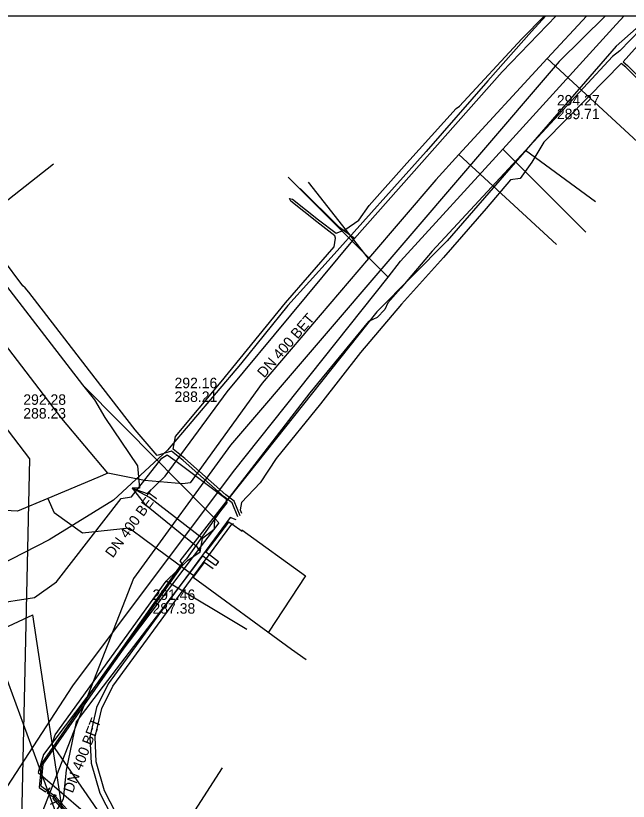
# Model space of a CAD drawing. Extents: x -600309 to -598967, y -1161267 to -1160292.
# Drawn here: x -600042.4 to -599995.5, y -1160352.5 to -1160292.3 of the extents above; entities that cross this region are included whole.
import ezdxf

# ---------------------------------------------------------------- set-up
doc = ezdxf.new("R2010")
doc.units = 0
for name, color, linetype in [('Vrstva 12', 7, 'Continuous'), ('Vrstva 13', 7, 'Continuous'), ('Vrstva 16', 7, 'Continuous'), ('Vrstva 42', 7, 'Continuous'), ('Vrstva 54', 7, 'Continuous'), ('Vrstva 55', 7, 'Continuous'), ('Vrstva 58', 7, 'Continuous'), ('Vrstva 63', 7, 'Continuous'), ('Vrstva 9', 7, 'Continuous')]:
    doc.layers.add(name, color=color, linetype=linetype)

msp = doc.modelspace()

# ---------------------------------------------------------------- linework, layer by layer
at = {"layer": 'Vrstva 12'}
for points in [[(-600016.43, -1160309.39), (-600005.11, -1160296.65), (-600000.985, -1160292.347)], [(-599994.53, -1160293.39), (-599996.1, -1160295.04), (-599996.67, -1160295.46), (-600003.33, -1160302.65)], [(-600003.33, -1160302.65), (-600010.47, -1160310.37), (-600012.87, -1160313.2), (-600013.87, -1160314.33), (-600014.09, -1160314.83), (-600014.67, -1160315.45), (-600015.35, -1160315.75), (-600019.84, -1160321.2), (-600027.14, -1160330.66), (-600027.16, -1160331.67), (-600028.05, -1160332.35)], [(-599997.96, -1160306.59), (-600003.33, -1160302.65)], [(-600050.01, -1160304.22), (-600047.46, -1160307.49), (-600045.75, -1160309.61), (-600037.23, -1160320.58)], [(-600016.43, -1160309.39), (-600017.56, -1160308.55), (-600020.57, -1160305.58)], [(-600033.44, -1160328.5), (-600032.29, -1160328.91), (-600030.92, -1160327.57), (-600026.17, -1160321.13), (-600016.43, -1160309.39)], [(-600037.23, -1160320.58), (-600036.33, -1160321.75), (-600035.54, -1160323.09)], [(-600035.54, -1160323.09), (-600033.04, -1160326.78), (-600032.89, -1160328.49), (-600033.44, -1160328.5)], [(-600033.44, -1160328.5), (-600032.5, -1160329.71), (-600028.55, -1160332.91), (-600028.23, -1160333.36)], [(-600028.05, -1160332.35), (-600032.11, -1160329.22), (-600033.44, -1160328.5)], [(-600028.23, -1160333.36), (-600028.05, -1160332.35)], [(-600030.83, -1160335.62), (-600029.2, -1160334.04), (-600028.23, -1160333.36)], [(-600038.37, -1160349.82), (-600039.57, -1160348.08), (-600039.33, -1160347.38), (-600030.83, -1160335.62)], [(-600024.65, -1160339.32), (-600030.83, -1160335.62)], [(-600034.32, -1160355.66), (-600038.37, -1160349.82)]]:
    msp.add_lwpolyline(points, dxfattribs=at)
at = {"layer": 'Vrstva 13'}
msp.add_line((-600013.85, -1160312.35), (-600021.488, -1160304.701), dxfattribs=at)
for points in [[(-600043.56, -1160352.1), (-600043.347, -1160351.853), (-600037.975, -1160343.616), (-600025.676, -1160327.214), (-600013.85, -1160312.35), (-600012.89, -1160311.139), (-600005.067, -1160302.555), (-599996.39, -1160293.01), (-599995.775, -1160292.347)], [(-600005.067, -1160302.555), (-600003.888, -1160303.735), (-599998.715, -1160308.921)], [(-600069.247, -1160326.845), (-600045.498, -1160308.427), (-600039.453, -1160303.674)], [(-600037.23, -1160320.58), (-600031.43, -1160326.46)], [(-600031.43, -1160326.46), (-600031.15, -1160326.74)], [(-600031.15, -1160326.74), (-600030.6, -1160327.29), (-600027.09, -1160330.85), (-600026.81, -1160331.14), (-600027.91, -1160332.59)], [(-600027.91, -1160332.59), (-600040.22, -1160348.89), (-600040.63, -1160350.26)], [(-600040.63, -1160350.26), (-600030.17, -1160359.23), (-600025.6, -1160362.3), (-600024.69, -1160362.9)], [(-600033.31, -1160361.09), (-600033.125, -1160360.829), (-600030.99, -1160356.83), (-600026.528, -1160349.897)]]:
    msp.add_lwpolyline(points, dxfattribs=at)
at = {"layer": 'Vrstva 16'}
for points in [[(-600035.295, -1160327.352), (-600038.83, -1160323.18), (-600047.7, -1160311.6), (-600047.5, -1160308.26), (-600050.81, -1160304.07), (-600053.96, -1160300), (-600058.4, -1160294.46), (-600059.974, -1160292.347)], [(-599998.63, -1160292.347), (-600001.66, -1160295.63), (-600008.42, -1160302.96), (-600010.2, -1160304.9), (-600015.34, -1160310.92), (-600023.48, -1160320.46), (-600029.01, -1160328.09), (-600029.55, -1160328.17), (-600032.491, -1160327.919)], [(-600001.66, -1160295.63), (-599994.42, -1160302.31)], [(-600008.42, -1160302.96), (-600000.94, -1160309.85)], [(-600015.34, -1160310.92), (-600019.94, -1160305.08)], [(-600032.491, -1160327.919), (-600035.295, -1160327.352), (-600036.066, -1160327.692), (-600039.894, -1160329.296), (-600042.22, -1160330.27), (-600044.183, -1160330.165)], [(-600039.894, -1160329.296), (-600039.418, -1160330.397)], [(-600028.684, -1160335.24), (-600032.359, -1160332.519), (-600033.671, -1160331.547), (-600037.23, -1160331.933), (-600039.418, -1160330.397)], [(-600038.95, -1160354.2), (-600047.112, -1160332.022)]]:
    msp.add_lwpolyline(points, dxfattribs=at)
at = {"layer": 'Vrstva 42'}
for points in [[(-599992.497, -1160292.347), (-599994.33, -1160294.17), (-599995.853, -1160295.866), (-599995.513, -1160296.146), (-599991.99, -1160299.688), (-599991.92, -1160299.9), (-599992.132, -1160299.829), (-599995.647, -1160296.294), (-599995.991, -1160296.011), (-599998.49, -1160298.54), (-600001.91, -1160302.03), (-600002.84, -1160303.55), (-600003.73, -1160304.81), (-600004.47, -1160304.9), (-600006.35, -1160307.11), (-600009.61, -1160310.86), (-600012.82, -1160314.42), (-600015.96, -1160318.13), (-600019.02, -1160322.04), (-600022.42, -1160326.24), (-600023.65, -1160328.08), (-600025.06, -1160329.6), (-600025.162, -1160330.166), (-600025.059, -1160330.405)], [(-600008.38, -1160299.26), (-600003.6, -1160294.12), (-600001.873, -1160292.347)], [(-600025.158, -1160330.611), (-600025.628, -1160329.497), (-600026.256, -1160329.003), (-600029.396, -1160326.233), (-600030.3, -1160325.508), (-600030.13, -1160324.55), (-600026.62, -1160320.35), (-600021.71, -1160314.31), (-600017.98, -1160310.02), (-600017.88, -1160309.38), (-600017.914, -1160309.186), (-600019.292, -1160308.129), (-600021.295, -1160306.543), (-600021.39, -1160306.34), (-600021.171, -1160306.386), (-600019.169, -1160307.971), (-600017.832, -1160308.996), (-600017.15, -1160308.72), (-600016.09, -1160308), (-600015.3, -1160306.87), (-600012.42, -1160303.62), (-600008.638, -1160299.458), (-600008.38, -1160299.26)], [(-600025.342, -1160330.689), (-600025.792, -1160329.623), (-600026.384, -1160329.157), (-600029.524, -1160326.387), (-600030.435, -1160325.655), (-600031.53, -1160325.99), (-600033.21, -1160324.04), (-600036.26, -1160320.09), (-600041.36, -1160313.5), (-600041.618, -1160313.159), (-600041.806, -1160313.022), (-600043.364, -1160310.92)], [(-600025.016, -1160331.803), (-600025.817, -1160331.264), (-600026.068, -1160331.095), (-600027.805, -1160333.371), (-600027.525, -1160333.581), (-600026.823, -1160334.108), (-600026.943, -1160334.268), (-600027.063, -1160334.428), (-600027.763, -1160333.903), (-600028.048, -1160333.689), (-600029.615, -1160335.742), (-600035.648, -1160343.647), (-600037.717, -1160346.386), (-600038.5, -1160350.08), (-600038.715, -1160352.302), (-600038.887, -1160352.567), (-600045.877, -1160363.329), (-600046.428, -1160364.177), (-600046.744, -1160364.664), (-600047.293, -1160365.509), (-600047.104, -1160366.293)], [(-600025.488, -1160330.929), (-600025.934, -1160330.756), (-600029.615, -1160335.742), (-600030.782, -1160337.323), (-600035.284, -1160343.462), (-600036.16, -1160345.27), (-600036.675, -1160347.553), (-600036.577, -1160349.54), (-600035.919, -1160351.841), (-600034.556, -1160354.457)], [(-600034.228, -1160354.223), (-600035.565, -1160351.657), (-600036.193, -1160349.432), (-600036.276, -1160347.536), (-600035.771, -1160345.361), (-600034.925, -1160343.639), (-600030.46, -1160337.56), (-600027.763, -1160333.903), (-600027.525, -1160333.581), (-600025.817, -1160331.264), (-600025.793, -1160331.232), (-600025.689, -1160331.199)], [(-600025.049, -1160331.679), (-600020.166, -1160335.219), (-600022.996, -1160339.512)], [(-600027.235, -1160334.663), (-600027.934, -1160334.186), (-600028.761, -1160335.319), (-600021.241, -1160340.811), (-600020.114, -1160341.6)], [(-600038.887, -1160352.567), (-600039.056, -1160352.403), (-600039.721, -1160352.71)]]:
    msp.add_lwpolyline(points, dxfattribs=at)
at = {"layer": 'Vrstva 54'}
for points in [[(-600047, -1160340.95), (-600041.05, -1160338.2)], [(-600038.581, -1160354.394), (-600041.05, -1160338.2)]]:
    msp.add_lwpolyline(points, dxfattribs=at)
at = {"layer": 'Vrstva 55'}
for points in [[(-599993.759, -1160292.347), (-599996.382, -1160294.682), (-600009.32, -1160309.58), (-600014.702, -1160315.013), (-600026.731, -1160330.129), (-600029.8, -1160334.07)], [(-600044.23, -1160337.37), (-600040.91, -1160336.86), (-600039.239, -1160335.66), (-600034.29, -1160329.29), (-600033.479, -1160329.17), (-600031.18, -1160326.21), (-600030.75, -1160325.94), (-600030.08, -1160326.43), (-600026.26, -1160329.28), (-600026.199, -1160329.62), (-600026.76, -1160330.34), (-600029.269, -1160333.9), (-600029.72, -1160334.365), (-600034.165, -1160340.659), (-600035.809, -1160342.986), (-600040.388, -1160349.579), (-600040.555, -1160351.393), (-600040.074, -1160351.736), (-600039.75, -1160351.42), (-600039.945, -1160351.802), (-600039.475, -1160352.109), (-600039.343, -1160351.933)], [(-600029.8, -1160334.07), (-600029.58, -1160334.375), (-600035.711, -1160343.054), (-600040.272, -1160349.621), (-600040.425, -1160351.287), (-600039.442, -1160351.994), (-600039.362, -1160351.93)], [(-600067.29, -1160346.5), (-600067.199, -1160346.47), (-600066.669, -1160346.56), (-600064.711, -1160348.129), (-600055.91, -1160355.18), (-600053.09, -1160357.55), (-600052.41, -1160358.71), (-600047.269, -1160362.99), (-600045.493, -1160363.742), (-600044.572, -1160363.562), (-600038.887, -1160354.86), (-600038.076, -1160353.846), (-600039.495, -1160352.239), (-600039.325, -1160351.941)], [(-600039.304, -1160351.965), (-600039.405, -1160352.16), (-600037.919, -1160353.842), (-600038.79, -1160354.93), (-600044.499, -1160363.67), (-600045.47, -1160363.86), (-600048.48, -1160365.05), (-600050.19, -1160366.52), (-600051.989, -1160369.75), (-600052.259, -1160370.08), (-600052.28, -1160370.18)], [(-600039.277, -1160351.979), (-600039.315, -1160352.08), (-600037.836, -1160353.755), (-600036.49, -1160355.3), (-600031.689, -1160359.56), (-600027.97, -1160362.61), (-600026.749, -1160362.74), (-600026.42, -1160363.63), (-600016.77, -1160369.93), (-600016.59, -1160370.1), (-600016.45, -1160370.056), (-600015.67, -1160370.36), (-600012.429, -1160373.09), (-600006.77, -1160376.69), (-599997.25, -1160382.69), (-599994.04, -1160384.98)]]:
    msp.add_lwpolyline(points, dxfattribs=at)
at = {"layer": 'Vrstva 58'}
msp.add_lwpolyline([(-600001.779, -1160292.347), (-600002.86, -1160293.55), (-600006.21, -1160297.33), (-600010.93, -1160302.75), (-600018.21, -1160310.85), (-600021.51, -1160314.51), (-600025.14, -1160319.01), (-600030.73, -1160325.59), (-600034.87, -1160329.42), (-600039.8, -1160332.45), (-600043.71, -1160334.44)], dxfattribs=at)
at = {"layer": 'Vrstva 63'}
msp.add_lwpolyline([(-600308.541, -1160292.347), (-598967.108, -1160292.347), (-598967.108, -1161267.031), (-600308.541, -1161267.031)], close=True, dxfattribs=at)
at = {"layer": 'Vrstva 9'}
for p, q in [((-600067.259, -1160292.347), (-600041.299, -1160326.259)), ((-599997.197, -1160292.347), (-600000.74, -1160295.85)), ((-600000.74, -1160295.85), (-600025.906, -1160325.214)), ((-600025.906, -1160325.214), (-600033.338, -1160335.405)), ((-600041.299, -1160326.259), (-600042, -1160357.52)), ((-600033.338, -1160335.405), (-600042, -1160357.52))]:
    msp.add_line(p, q, dxfattribs=at)

# ---------------------------------------------------------------- texts
at = {"layer": 'Vrstva 12'}
for s, p in [('294.27', (-600000.922, -1160299.213)), ('289.71', (-600000.922, -1160300.263)), ('292.16', (-600030.194, -1160320.85)), ('292.28', (-600041.773, -1160322.121)), ('288.21', (-600030.194, -1160321.9)), ('288.23', (-600041.773, -1160323.171)), ('291.46', (-600031.883, -1160337.052)), ('287.38', (-600031.883, -1160338.102))]:
    msp.add_text(s, height=0.8, dxfattribs=at).set_placement(p)
for rotation, p in [(49.27437, (-600023.336, -1160320.112)), (53.61993, (-600034.921, -1160333.887)), (68.60549, (-600037.994, -1160351.883))]:
    msp.add_text('DN 400 BET', height=0.8, rotation=rotation, dxfattribs=at).set_placement(p)

doc.saveas('drawing.dxf')
